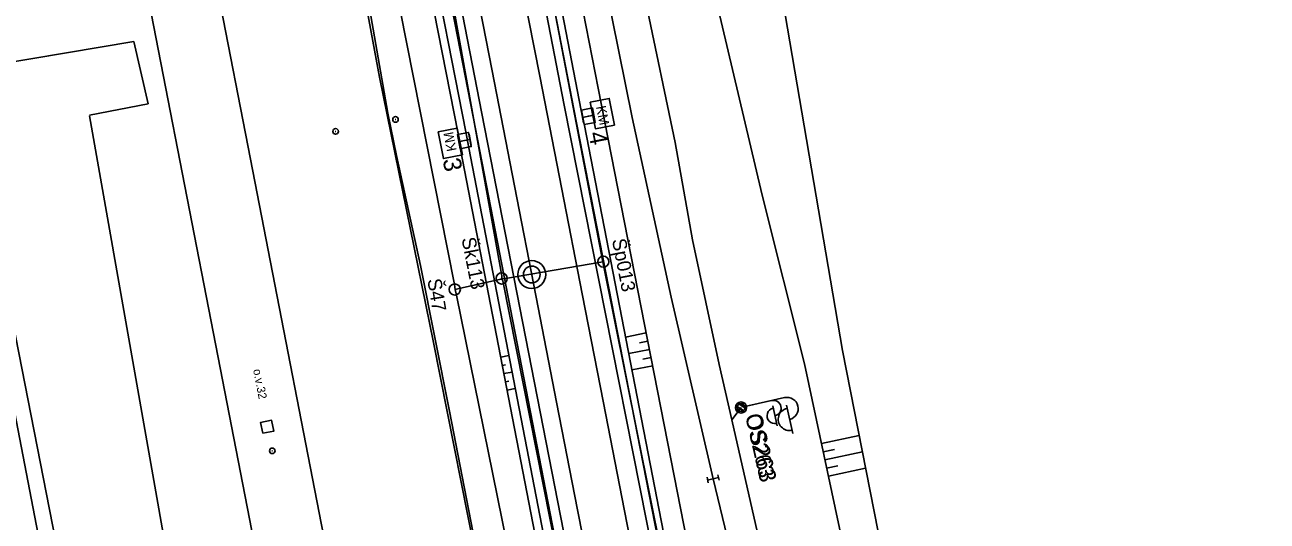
# Model space of a CAD drawing. Extents: x -545967 to -545044, y -1122650 to -1118491.
# Drawn here: x -545804.3 to -545693, y -1119007.5 to -1118963 of the extents above; entities that cross this region are included whole.
import ezdxf

# ---------------------------------------------------------------- set-up
doc = ezdxf.new("R2010")
doc.units = 0
for name, color, linetype in [('Vrstva 1', 7, 'Continuous'), ('Vrstva 1 - Koleje', 7, 'Continuous'), ('Vrstva 11 - Trakce', 7, 'Continuous'), ('Vrstva 12 - Trakce zaklady', 7, 'Continuous'), ('Vrstva 19 - Staniceni', 7, 'Continuous'), ('Vrstva 25', 7, 'Continuous'), ('Vrstva 25 - silnoproud prvky', 7, 'Continuous'), ('Vrstva 26', 7, 'Continuous'), ('Vrstva 26 - silnoproud', 7, 'Continuous'), ('Vrstva 28', 7, 'Continuous'), ('Vrstva 28 - zabzar', 7, 'Continuous'), ('Vrstva 3', 7, 'Continuous'), ('Vrstva 32', 7, 'Continuous'), ('Vrstva 4 - Teren - stezky - prechody - plochy', 7, 'Continuous'), ('Vrstva 43', 7, 'Continuous'), ('Vrstva 44', 7, 'Continuous'), ('Vrstva 48', 7, 'Continuous'), ('Vrstva 49', 7, 'Continuous'), ('Vrstva 50', 7, 'Continuous'), ('Vrstva 62', 7, 'Continuous')]:
    doc.layers.add(name, color=color, linetype=linetype)

msp = doc.modelspace()

# ---------------------------------------------------------------- linework, layer by layer
at = {"layer": 'Vrstva 1'}
for points in [[(-545803.34, -1118697.36), (-545802.53, -1118701.56), (-545796.37, -1118733.14), (-545788.89, -1118771.63), (-545784.12, -1118796.19), (-545777.72, -1118829.09), (-545771.16, -1118862.7), (-545764.79, -1118895.38), (-545757.6, -1118932.31), (-545753.44, -1118953.65), (-545749.9, -1118971.29), (-545746.4, -1118987.4), (-545742.64, -1119003.66), (-545739.31, -1119017.41), (-545736, -1119030.1), (-545730.53, -1119049.44)], [(-545838.41, -1118714.77), (-545838.26, -1118718.35), (-545837.49, -1118728.28), (-545836.89, -1118733.39), (-545834.73, -1118746.88), (-545830.84, -1118767.19), (-545826.73, -1118788.32), (-545823.14, -1118806.83), (-545818.08, -1118832.89), (-545813.11, -1118858.45), (-545808.53, -1118881.99), (-545803.06, -1118910.12), (-545797.6, -1118938.25), (-545792.14, -1118966.4), (-545787.42, -1118990.65), (-545782.57, -1119015.55), (-545777.21, -1119043), (-545771.69, -1119071.3)], [(-545838.41, -1118714.77), (-545838.26, -1118718.35), (-545837.49, -1118728.28), (-545836.89, -1118733.39), (-545834.73, -1118746.88), (-545830.84, -1118767.19), (-545826.73, -1118788.32), (-545823.14, -1118806.83), (-545818.08, -1118832.89), (-545813.11, -1118858.45), (-545808.53, -1118881.99), (-545803.06, -1118910.12), (-545797.6, -1118938.25), (-545792.14, -1118966.4), (-545787.42, -1118990.65), (-545782.57, -1119015.55), (-545777.21, -1119043), (-545771.69, -1119071.3)], [(-545833.04, -1118722.99), (-545832.61, -1118725.22), (-545828.16, -1118748.16), (-545821.79, -1118781.06), (-545814.8, -1118816.97), (-545807.18, -1118856.23), (-545801.35, -1118886.26), (-545795.99, -1118913.81), (-545789.89, -1118945.22), (-545784.09, -1118975.02), (-545776.35, -1119014.88), (-545771.03, -1119042.2)]]:
    msp.add_lwpolyline(points, dxfattribs=at)
at = {"layer": 'Vrstva 1 - Koleje'}
for points in [[(-545764.38, -1118957.16), (-545762.44, -1118967.11), (-545760.44, -1118977.41), (-545758.49, -1118987.39), (-545756.66, -1118996.8), (-545754.78, -1119006.44), (-545753.33, -1119013.87), (-545751.55, -1119023), (-545750.77, -1119027.01), (-545749.86, -1119031.7), (-545747.99, -1119041.33), (-545746.14, -1119050.89), (-545744.24, -1119060.74), (-545742.57, -1119069.43), (-545740.71, -1119079.14), (-545738.92, -1119088.42), (-545738.2, -1119092.23), (-545736.39, -1119101.71)], [(-545760.16, -1118957.41), (-545758.17, -1118967.59), (-545756.2, -1118977.71), (-545754.37, -1118987.08), (-545752.46, -1118996.85), (-545750.61, -1119006.38), (-545748.68, -1119016.27), (-545747.06, -1119024.53), (-545746.7, -1119026.42), (-545745.62, -1119031.96), (-545743.71, -1119041.72), (-545741.69, -1119052.08), (-545739.62, -1119062.69), (-545737.59, -1119073.15), (-545735.6, -1119083.35), (-545734, -1119091.55), (-545732.95, -1119096.94)]]:
    msp.add_lwpolyline(points, dxfattribs=at)
at = {"layer": 'Vrstva 11 - Trakce'}
for p, q in [((-545753.45, -1118970.59), (-545753.26, -1118971.57)), ((-545754.43, -1118970.79), (-545754.24, -1118971.77)), ((-545753.35, -1118971.08), (-545754.34, -1118971.28)), ((-545764.51, -1118972.78), (-545764.32, -1118973.76)), ((-545765.49, -1118972.96), (-545765.3, -1118973.95)), ((-545764.42, -1118973.27), (-545765.4, -1118973.45))]:
    msp.add_line(p, q, dxfattribs=at)
at = {"layer": 'Vrstva 12 - Trakce zaklady'}
for p, q in [((-545754.44, -1118970.62), (-545753.46, -1118970.43)), ((-545754.18, -1118971.92), (-545753.2, -1118971.72)), ((-545765.55, -1118972.81), (-545764.57, -1118972.62)), ((-545765.31, -1118974.09), (-545764.32, -1118973.9))]:
    msp.add_line(p, q, dxfattribs=at)
for points in [[(-545754.18, -1118971.92), (-545754.44, -1118970.62), (-545753.46, -1118970.43), (-545753.2, -1118971.72), (-545754.18, -1118971.92)], [(-545754.44, -1118970.62), (-545754.44, -1118970.62), (-545754.18, -1118971.92), (-545754.18, -1118971.92)], [(-545764.57, -1118972.62), (-545764.32, -1118973.9), (-545765.31, -1118974.09), (-545765.55, -1118972.81), (-545764.57, -1118972.62)], [(-545764.57, -1118972.62), (-545764.57, -1118972.62), (-545764.32, -1118973.9), (-545764.32, -1118973.9)]]:
    msp.add_lwpolyline(points, dxfattribs=at)
at = {"layer": 'Vrstva 19 - Staniceni'}
for p, q in [((-545753.84, -1118971.18), (-545753.42, -1118971.1)), ((-545764.91, -1118973.36), (-545765.34, -1118973.44))]:
    msp.add_line(p, q, dxfattribs=at)
for points in [[(-545753.65, -1118969.9), (-545751.95, -1118969.57), (-545751.48, -1118971.96), (-545753.18, -1118972.3)], [(-545765.1, -1118974.64), (-545766.81, -1118974.97), (-545767.27, -1118972.58), (-545765.57, -1118972.24)]]:
    msp.add_lwpolyline(points, close=True, dxfattribs=at)
for radius in [1.25, 0.752]:
    msp.add_circle((-545758.89, -1118985.36), radius, dxfattribs=at)
at = {"layer": 'Vrstva 25'}
for p, q in [((-545740.61, -1118997.15), (-545739.8, -1118997.66)), ((-545740.38, -1118996.85), (-545739.63, -1118997.32)), ((-545739.64, -1118997.17), (-545736.23, -1118996.39)), ((-545736.07, -1118997.07), (-545735.5, -1118999.61))]:
    msp.add_line(p, q, dxfattribs=at)
msp.add_lwpolyline([(-545783, -1118999.59), (-545783.19, -1118998.61), (-545782.21, -1118998.42), (-545782.02, -1118999.4)], close=True, dxfattribs=at)
msp.add_circle((-545740.13, -1118997.28), 0.5, dxfattribs=at)
msp.add_circle((-545740.13, -1118997.28), 0.5, dxfattribs=at)
for centre, start, end in [((-545735.8, -1118998.34), 102.1781, 283.5832), ((-545736.01, -1118997.37), 282.8806, 102.8806)]:
    msp.add_arc(centre, 1, start, end, dxfattribs=at)
at = {"layer": 'Vrstva 25 - silnoproud prvky'}
for p, q in [((-545740.47, -1118997.19), (-545739.9, -1118997.54)), ((-545740.3, -1118996.98), (-545739.78, -1118997.31)), ((-545739.79, -1118997.2), (-545737.4, -1118996.66)), ((-545737.29, -1118997.14), (-545736.89, -1118998.91))]:
    msp.add_line(p, q, dxfattribs=at)
msp.add_circle((-545740.13, -1118997.28), 0.35, dxfattribs=at)
for centre, start, end in [((-545737.1, -1118998.02), 102.1781, 283.5832), ((-545737.24, -1118997.34), 282.8806, 102.8806)]:
    msp.add_arc(centre, 0.7, start, end, dxfattribs=at)
at = {"layer": 'Vrstva 26'}
for points in [[(-545712.5, -1119096.16), (-545714.8, -1119089.4), (-545718.28, -1119079.35), (-545722.62, -1119065.29), (-545724.09, -1119058.69), (-545725.37, -1119053.85), (-545726.48, -1119050.78), (-545727.45, -1119048.73), (-545727.23, -1119047.02), (-545727.52, -1119045.59), (-545729.03, -1119043.07), (-545733.36, -1119028.89), (-545737.61, -1119013.08), (-545738.97, -1119007.19), (-545740.97, -1118998.37), (-545742.1, -1118993.41), (-545744.47, -1118982.24), (-545746.04, -1118973.54), (-545748.64, -1118961.1)], [(-545740.97, -1118998.37), (-545740.13, -1118997.28)]]:
    msp.add_lwpolyline(points, dxfattribs=at)
at = {"layer": 'Vrstva 26 - silnoproud'}
for points in [[(-545800.9, -1118821.51), (-545796.68, -1118843.32), (-545791.19, -1118870.63), (-545788.65, -1118883.96), (-545784.72, -1118904.4), (-545780.64, -1118924.89), (-545776.9, -1118944.08), (-545772.53, -1118967.67), (-545767.71, -1118991.46), (-545763.38, -1119013.33), (-545759.75, -1119031.81), (-545755.58, -1119054.34), (-545752.32, -1119069.69), (-545748.72, -1119088.79), (-545745.5, -1119105.78)], [(-545712.5, -1119096.16), (-545714.8, -1119089.4), (-545718.28, -1119079.35), (-545722.62, -1119065.29), (-545724.09, -1119058.69), (-545725.37, -1119053.85), (-545726.48, -1119050.78), (-545727.45, -1119048.73), (-545727.23, -1119047.02), (-545727.52, -1119045.59), (-545729.03, -1119043.07), (-545733.36, -1119028.89), (-545737.61, -1119013.08), (-545738.97, -1119007.19), (-545740.97, -1118998.37), (-545742.1, -1118993.41), (-545744.47, -1118982.24), (-545746.04, -1118973.54), (-545748.64, -1118961.1)], [(-545740.97, -1118998.37), (-545740.13, -1118997.28)]]:
    msp.add_lwpolyline(points, dxfattribs=at)
at = {"layer": 'Vrstva 28'}
msp.add_line((-545782.18, -1119001.16), (-545782.13, -1119001.16), dxfattribs=at)
msp.add_circle((-545782.15, -1119001.16), 0.25, dxfattribs=at)
at = {"layer": 'Vrstva 28 - zabzar'}
msp.add_lwpolyline([(-545759.72, -1119031.91), (-545759.89, -1119030.77), (-545763.23, -1119013.33), (-545766.25, -1118997.62), (-545768.86, -1118984.55), (-545771, -1118974.69), (-545771.8, -1118970.9), (-545773.86, -1118959.07), (-545776.3, -1118946.17), (-545780.31, -1118924.98), (-545785.87, -1118897.11), (-545790.99, -1118870.65), (-545796.29, -1118843.25), (-545799.19, -1118827.63), (-545805.85, -1118794.17), (-545808.2, -1118783.5), (-545812.82, -1118758.82), (-545816.62, -1118739.16), (-545820.43, -1118719.58), (-545822.89, -1118707.67), (-545825.23, -1118696.09)], dxfattribs=at)
at = {"layer": 'Vrstva 3'}
for p, q in [((-545743.07, -1119004.02), (-545743.18, -1119003.53)), ((-545743.13, -1119003.78), (-545742.15, -1119003.55)), ((-545742.1, -1119003.79), (-545742.21, -1119003.31))]:
    msp.add_line(p, q, dxfattribs=at)
at = {"layer": 'Vrstva 32'}
msp.add_lwpolyline([(-545746.9, -1119097.66), (-545750.31, -1119079.79), (-545751.4, -1119074.13), (-545752.97, -1119065.38), (-545755.29, -1119054.49), (-545758.65, -1119036.78), (-545759.72, -1119031.91), (-545759.89, -1119030.77), (-545763.23, -1119013.33), (-545766.25, -1118997.62), (-545768.86, -1118984.55), (-545771, -1118974.69), (-545771.8, -1118970.9), (-545773.86, -1118959.07), (-545776.3, -1118946.17), (-545780.31, -1118924.98), (-545785.87, -1118897.11), (-545790.99, -1118870.65), (-545796.29, -1118843.25), (-545799.19, -1118827.63)], dxfattribs=at)
at = {"layer": 'Vrstva 4 - Teren - stezky - prechody - plochy'}
for points in [[(-545842.99, -1118523.92), (-545841.7, -1118530.4), (-545836.85, -1118554.45), (-545831.05, -1118584.6), (-545819.35, -1118645.26), (-545811.23, -1118686.91), (-545799.53, -1118746.65), (-545788.53, -1118802.77), (-545777.85, -1118857.7), (-545765.83, -1118919.34), (-545755.98, -1118970.18), (-545745.51, -1119023.12), (-545734.81, -1119078.88), (-545723.15, -1119138.68), (-545711.33, -1119199.26), (-545707.51, -1119218.93), (-545706.35, -1119218.8)], [(-545711.32, -1119247.44), (-545711.9, -1119243.96), (-545720.22, -1119201.67), (-545721.28, -1119195.76), (-545731.55, -1119141.71), (-545737.08, -1119112.42), (-545743.44, -1119079.1), (-545754.28, -1119022.01), (-545764.13, -1118971.24), (-545774.7, -1118917.12), (-545786.1, -1118858.18), (-545797, -1118803.41), (-545807.66, -1118749.42), (-545819.91, -1118686.43), (-545828.53, -1118641.36), (-545850.15, -1118530.53), (-545851.16, -1118525.52)], [(-545710.22, -1119247.22), (-545719, -1119201.39), (-545730.62, -1119141.39), (-545736.21, -1119112.21), (-545742.56, -1119078.93), (-545753.41, -1119021.81), (-545763.36, -1118970.94), (-545773.92, -1118916.71), (-545785.33, -1118858.19), (-545796.21, -1118802.91), (-545806.84, -1118748.63), (-545819.21, -1118686.19), (-545827.82, -1118641.01), (-545849.34, -1118530.25), (-545850.41, -1118525.37)], [(-545787.71, -1118802.92), (-545777.14, -1118857.58), (-545765.12, -1118918.89), (-545755.12, -1118970.55), (-545744.47, -1119024.93), (-545734.12, -1119078.34), (-545722.33, -1119138.41), (-545711.22, -1119196.15), (-545707.54, -1119214.27), (-545707.41, -1119215.2), (-545706.35, -1119218.8)]]:
    msp.add_lwpolyline(points, dxfattribs=at)
at = {"layer": 'Vrstva 43'}
for centre in [(-545752.48, -1118984.21), (-545765.79, -1118986.7), (-545761.59, -1118985.71)]:
    msp.add_circle(centre, 0.5, dxfattribs=at)
at = {"layer": 'Vrstva 44'}
for points in [[(-545799.29, -1118815.32), (-545789.93, -1118863.75), (-545789.78, -1118864), (-545789.77, -1118864.31), (-545781.74, -1118904.71), (-545781.69, -1118905.06), (-545781.68, -1118905.37), (-545773.84, -1118945.46), (-545773.73, -1118945.72), (-545773.75, -1118946.11), (-545765.82, -1118986.25), (-545765.77, -1118986.71), (-545765.63, -1118987.21), (-545755.04, -1119039.46), (-545755.01, -1119039.88), (-545755.03, -1119040.22), (-545744.16, -1119093.43), (-545744.1, -1119093.78), (-545744.06, -1119094.17), (-545734.82, -1119146.14)], [(-545766.7, -1118910.67), (-545758.96, -1118950.56), (-545752.53, -1118984.22), (-545761.24, -1118985.73), (-545761.57, -1118985.76)], [(-545775.68, -1118912.68), (-545767.61, -1118951.88), (-545761.58, -1118985.48), (-545761.57, -1118985.76)], [(-545730.08, -1119098.83), (-545737.37, -1119060.45), (-545745.2, -1119020.61), (-545752.53, -1118984.22)], [(-545761.57, -1118985.76), (-545761.67, -1118985.78), (-545765.39, -1118986.62), (-545765.77, -1118986.71)], [(-545739.31, -1119100.74), (-545746.71, -1119061.8), (-545754.21, -1119022.59), (-545761.47, -1118985.92), (-545761.57, -1118985.76)]]:
    msp.add_lwpolyline(points, dxfattribs=at)
at = {"layer": 'Vrstva 48'}
for p, q in [((-545748.63, -1118990.6), (-545750.48, -1118990.96)), ((-545748.49, -1118991.33), (-545749.23, -1118991.48)), ((-545761.67, -1118992.77), (-545760.94, -1118992.62)), ((-545748.34, -1118992.07), (-545750.2, -1118992.43)), ((-545748.2, -1118992.81), (-545748.94, -1118992.95)), ((-545761.53, -1118993.5), (-545761.24, -1118993.45)), ((-545748.05, -1118993.54), (-545749.91, -1118993.91)), ((-545761.39, -1118994.24), (-545760.66, -1118994.1)), ((-545761.24, -1118994.98), (-545760.95, -1118994.92)), ((-545761.1, -1118995.71), (-545760.37, -1118995.57)), ((-545732.93, -1119000.51), (-545729.55, -1118999.79)), ((-545732.77, -1119001.24), (-545731.76, -1119001.03)), ((-545732.62, -1119001.98), (-545729.26, -1119001.26)), ((-545732.46, -1119002.71), (-545731.46, -1119002.5)), ((-545732.31, -1119003.44), (-545728.97, -1119002.73))]:
    msp.add_line(p, q, dxfattribs=at)
at = {"layer": 'Vrstva 49'}
for points in [[(-545839.31, -1118523.2), (-545838.1, -1118529.58), (-545837.4, -1118533.49), (-545832.71, -1118555.7), (-545825.14, -1118594.38), (-545814.25, -1118651.35), (-545808.03, -1118685.15), (-545795.16, -1118750.19), (-545783.94, -1118809.71), (-545774.85, -1118856.95), (-545763.42, -1118915.04), (-545752.93, -1118968.66), (-545741.71, -1119025.95), (-545730.22, -1119081.99), (-545719, -1119141.33), (-545708.86, -1119196.83), (-545704.64, -1119214.15)], [(-545795.7, -1118699.53), (-545788.23, -1118737.74), (-545783.17, -1118774.2), (-545777.68, -1118791.96), (-545766.25, -1118834.9), (-545762.23, -1118863.52), (-545750.54, -1118910.15), (-545748.76, -1118933.68), (-545738.23, -1118978.24), (-545734.45, -1118993.37), (-545726.8, -1119029.27), (-545708.68, -1119069.73), (-545699.17, -1119099.96), (-545685.31, -1119124.18), (-545683.36, -1119136.06), (-545688.07, -1119145.8), (-545688.34, -1119153.09)], [(-545785.57, -1118809.02), (-545776.46, -1118857.74), (-545776.22, -1118859.03), (-545764.99, -1118916.44), (-545764.66, -1118917.89), (-545754.45, -1118970.66), (-545754.17, -1118971.99), (-545744.32, -1119022.63), (-545744.06, -1119023.95), (-545733.43, -1119078.43), (-545721.62, -1119138.52), (-545721.39, -1119139.74), (-545710.15, -1119197.12), (-545709.97, -1119198.73), (-545706.79, -1119214.14), (-545707.41, -1119215.2), (-545706.35, -1119218.8), (-545705.86, -1119218.83), (-545705.11, -1119218.76), (-545703.5, -1119218.63), (-545703.07, -1119219.32), (-545701.68, -1119223.93)], [(-545712.35, -1119247.64), (-545712.92, -1119244.63), (-545721.55, -1119201.11), (-545732.64, -1119141.94), (-545733.19, -1119140.67), (-545738.44, -1119113.17), (-545744.26, -1119082.79), (-545744.78, -1119080.35), (-545754.15, -1119031.65), (-545755.21, -1119026.18), (-545765.27, -1118974.15), (-545765.5, -1118972.76), (-545775.82, -1118920.18), (-545776.08, -1118918.77), (-545787.25, -1118861.28), (-545787.56, -1118859.78), (-545796.82, -1118811)], [(-545711.32, -1119247.44), (-545711.9, -1119243.96), (-545720.22, -1119201.67), (-545721.28, -1119195.76), (-545721.94, -1119195.52), (-545732.08, -1119141.82), (-545732.26, -1119140.52), (-545737.74, -1119112.72), (-545743.31, -1119083.13), (-545744.04, -1119079.56), (-545753.26, -1119031.33), (-545754, -1119028.94), (-545754.15, -1119025.93), (-545754.49, -1119024.32), (-545754.82, -1119024.3), (-545764.54, -1118973.99), (-545764.79, -1118972.58), (-545775.11, -1118920.03), (-545775.4, -1118918.54), (-545786.58, -1118861.09), (-545786.92, -1118859.55), (-545796.32, -1118810.9)], [(-545740.89, -1118934.35), (-545731.05, -1118992.18), (-545723.95, -1119028.16), (-545702.93, -1119068.12), (-545693.56, -1119095.87)]]:
    msp.add_lwpolyline(points, dxfattribs=at)
at = {"layer": 'Vrstva 50'}
for p, q in [((-545771.13, -1118971.46), (-545771.08, -1118971.46)), ((-545776.5, -1118972.53), (-545776.45, -1118972.53))]:
    msp.add_line(p, q, dxfattribs=at)
for centre in [(-545771.1, -1118971.46), (-545776.47, -1118972.53)]:
    msp.add_circle(centre, 0.25, dxfattribs=at)
at = {"layer": 'Vrstva 62'}
for points in [[(-545831.33, -1118868.06), (-545823.58, -1118887.99), (-545813.29, -1118951.47), (-545805.4, -1118996.87), (-545793.32, -1119059.59), (-545786.9, -1119091.55)], [(-545774.89, -1119065.04), (-545773.28, -1119073.59), (-545788.35, -1119076.78), (-545809.85, -1118967.05), (-545794.57, -1118964.48), (-545793.28, -1118970.05)], [(-545798.52, -1118971.08), (-545793.28, -1118970.05)], [(-545798.52, -1118971.14), (-545781.74, -1119066.31)]]:
    msp.add_lwpolyline(points, dxfattribs=at)

# ---------------------------------------------------------------- texts
at = {"layer": 'Vrstva 11 - Trakce'}
for s, rotation, p in [('4', 281.1907, (-545753.82, -1118972.69)), ('3', 280.8173, (-545766.88, -1118975.07))]:
    msp.add_text(s, height=1.6, rotation=rotation, dxfattribs=at).set_placement(p)
at = {"layer": 'Vrstva 19 - Staniceni'}
for rotation, p in [(281.082, (-545753.13, -1118970.32)), (100.9803, (-545765.62, -1118974.23))]:
    msp.add_text('KM', height=0.873, rotation=rotation, dxfattribs=at).set_placement(p)
at = {"layer": 'Vrstva 25'}
for s, height, rotation, p in [('o.v.32', 0.75, 281.0236, (-545783.87, -1118993.9)), ('OS263', 1.5, 282.8806, (-545739.77, -1118998))]:
    msp.add_text(s, height=height, rotation=rotation, dxfattribs=at).set_placement(p)
at = {"layer": 'Vrstva 25 - silnoproud prvky'}
msp.add_text('OS263', height=1.4, rotation=282.8806, dxfattribs=at).set_placement((-545739.77, -1118998))
at = {"layer": 'Vrstva 43'}
for s, rotation, p in [('Šk113', 280.9998, (-545765.19, -1118982.13)), ('Šp013', 280.9998, (-545751.71, -1118982.25)), ('Š47', 279.317, (-545768.25, -1118985.82))]:
    msp.add_text(s, height=1.25, rotation=rotation, dxfattribs=at).set_placement(p)

doc.saveas('drawing.dxf')
